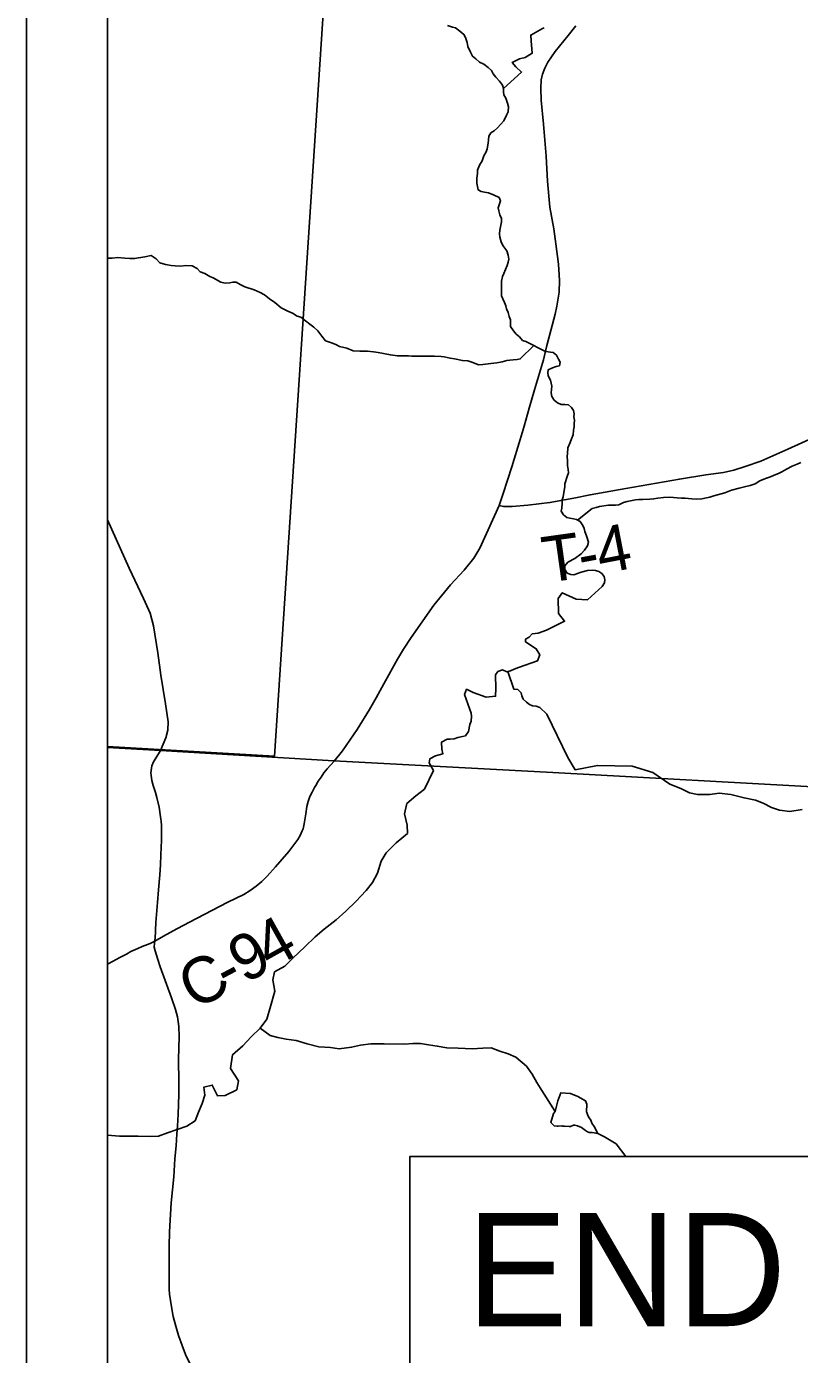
# Model space of a CAD drawing. Extents: x 0 to 34, y 0 to 22.
# Drawn here: x 23.917 to 24.872, y 17.319 to 18.961 of the extents above; entities that cross this region are included whole.
import ezdxf

# ---------------------------------------------------------------- set-up
doc = ezdxf.new("R2010")
doc.units = 0
for name, color, linetype in [('GM_X_Adjacent_County', 7, 'Continuous'), ('GM_X_County', 7, 'Continuous'), ('GM_X_County_Road', 7, 'Continuous'), ('GM_X_County_Road_Text', 7, 'Continuous'), ('GM_X_Minor_Lake', 7, 'Continuous'), ('GM_X_Minor_River', 7, 'Continuous'), ('GM_X_Section', 7, 'Continuous'), ('GM_X_Township', 7, 'Continuous'), ('GM_X_Township_Road', 7, 'Continuous'), ('GM_X_Township_Road_Text', 7, 'Continuous'), ('SH_Data', 7, 'Continuous'), ('SH_Text', 7, 'Continuous')]:
    doc.layers.add(name, color=color, linetype=linetype)

msp = doc.modelspace()

# ---------------------------------------------------------------- linework, layer by layer
at = {"layer": 'GM_X_Adjacent_County'}
for points in [[(30.8167, 17.8174), (30.8167, 20.9), (24.0167, 20.9), (24.0167, 18.0693)], [(24.0167, 18.0693), (24.0167, 14.1), (30.8167, 14.1), (30.8167, 17.8174)], [(25.5999, 17.9814), (24.5675, 18.0386), (24.2964, 18.0528), (24.0824, 18.0658), (24.0167, 18.0693)], [(24.0167, 18.0693), (24.0824, 18.0658), (24.2964, 18.0528), (24.5675, 18.0386), (25.5999, 17.9814)]]:
    msp.add_lwpolyline(points, dxfattribs=at)
at = {"layer": 'GM_X_County'}
for points in [[(30.8167, 17.8174), (30.8167, 20.9), (24.0167, 20.9), (24.0167, 18.0693)], [(24.0167, 18.0693), (24.0824, 18.0658), (24.2964, 18.0528), (24.5675, 18.0386), (25.5999, 17.9814)], [(24.0167, 18.0693), (24.0167, 14.1), (30.8167, 14.1), (30.8167, 17.8174)], [(25.5999, 17.9814), (24.5675, 18.0386), (24.2964, 18.0528), (24.0824, 18.0658), (24.0167, 18.0693)]]:
    msp.add_lwpolyline(points, dxfattribs=at)
at = {"layer": 'GM_X_County_Road'}
for points in [[(24.5957, 18.962), (24.5865, 18.9501), (24.5704, 18.9303), (24.561, 18.9168), (24.5573, 18.9095), (24.5544, 18.9023), (24.553, 18.8952), (24.5525, 18.8844), (24.553, 18.87), (24.556, 18.8404), (24.559, 18.8009), (24.5608, 18.7697), (24.5635, 18.7377), (24.5686, 18.7109), (24.5711, 18.6923), (24.5743, 18.6673), (24.5757, 18.6471), (24.5753, 18.6326), (24.5725, 18.6152), (24.5704, 18.6055), (24.5649, 18.5851), (24.5599, 18.5667), (24.5557, 18.549), (24.5447, 18.5119), (24.5383, 18.4891), (24.5319, 18.4669), (24.5268, 18.4503), (24.5166, 18.4166), (24.5058, 18.3837), (24.501, 18.3689), (24.4876, 18.3387), (24.4772, 18.3159), (24.4698, 18.3036), (24.4576, 18.2889), (24.441, 18.2704), (24.4203, 18.2453), (24.3924, 18.2054), (24.3827, 18.1911), (24.3753, 18.1787), (24.3583, 18.1481), (24.349, 18.1307), (24.3405, 18.1162), (24.3255, 18.0918), (24.3072, 18.0654), (24.2971, 18.0525)], [(24.0754, 17.8299), (24.0859, 17.836), (24.1023, 17.8451), (24.1269, 17.858), (24.1656, 17.8781), (24.1851, 17.8878), (24.1931, 17.8925), (24.2007, 17.8978), (24.2077, 17.9038), (24.2143, 17.9103), (24.2246, 17.9219), (24.2408, 17.9408), (24.2485, 17.9505), (24.2521, 17.9555), (24.2551, 17.9607), (24.2575, 17.9662), (24.2585, 17.969), (24.2599, 17.975), (24.2618, 17.9873), (24.2634, 17.9965), (24.2649, 18.0026), (24.2669, 18.0086), (24.2696, 18.0143), (24.2727, 18.0198), (24.2743, 18.0224), (24.2774, 18.0277), (24.2808, 18.0328), (24.2844, 18.0379), (24.2863, 18.0404), (24.2883, 18.0429), (24.2971, 18.0525)], [(24.1184, 17.3077), (24.1131, 17.3188), (24.1089, 17.3299), (24.1045, 17.3422), (24.1013, 17.3538), (24.098, 17.3655), (24.0957, 17.3778), (24.0935, 17.3932), (24.0931, 17.3995), (24.0928, 17.4277), (24.0929, 17.4525), (24.0936, 17.4705), (24.0953, 17.5061), (24.0986, 17.5385), (24.1, 17.5605), (24.1015, 17.5766), (24.1024, 17.5914), (24.1031, 17.6011), (24.104, 17.6161), (24.1044, 17.6278), (24.105, 17.6407), (24.1051, 17.6561), (24.1045, 17.6834), (24.1052, 17.712), (24.1049, 17.7243), (24.1043, 17.7304), (24.1032, 17.7365), (24.1007, 17.7453), (24.0957, 17.76), (24.0818, 17.798), (24.0788, 17.807), (24.0755, 17.8178), (24.0746, 17.8225), (24.0749, 17.8272), (24.0754, 17.8299)]]:
    msp.add_lwpolyline(points, dxfattribs=at)
at = {"layer": 'GM_X_Minor_Lake'}
for points in [[(24.6232, 17.5922), (24.6184, 17.6007), (24.6154, 17.6046), (24.6142, 17.6084), (24.6123, 17.6115), (24.6107, 17.6142), (24.6092, 17.618), (24.6088, 17.6187), (24.6092, 17.6283), (24.6077, 17.6325), (24.5981, 17.6379), (24.5893, 17.6413), (24.5774, 17.6425), (24.5736, 17.6325), (24.5701, 17.6194)], [(24.5701, 17.6194), (24.5682, 17.6168), (24.5647, 17.6057), (24.5689, 17.6015), (24.5728, 17.6011), (24.5739, 17.6011), (24.5785, 17.6015), (24.5797, 17.6011), (24.5819, 17.6011), (24.5877, 17.6007), (24.5892, 17.6007), (24.5931, 17.6022), (24.5946, 17.6022), (24.5977, 17.6015), (24.603, 17.5996), (24.6076, 17.5957), (24.6103, 17.5942), (24.6122, 17.5934), (24.616, 17.5934), (24.6232, 17.5922)]]:
    msp.add_lwpolyline(points, dxfattribs=at)
at = {"layer": 'GM_X_Minor_River'}
for points in [[(24.5582, 18.5591), (24.5341, 18.5716), (24.53, 18.5727), (24.5262, 18.5772), (24.522, 18.5807), (24.5189, 18.5848), (24.5151, 18.5901), (24.5151, 18.5985), (24.5135, 18.6023), (24.512, 18.6076), (24.5101, 18.6118), (24.5093, 18.6156), (24.5074, 18.6197), (24.5055, 18.6243), (24.504, 18.6281), (24.5039, 18.6463), (24.5051, 18.652), (24.5069, 18.6558), (24.5107, 18.6657), (24.5122, 18.6695), (24.513, 18.6733), (24.5122, 18.6782), (24.5103, 18.6835), (24.5057, 18.6903), (24.5034, 18.6949), (24.5019, 18.7006), (24.5015, 18.7047), (24.5019, 18.7093), (24.503, 18.7154), (24.5037, 18.7195), (24.5037, 18.7237), (24.5018, 18.7283), (24.5007, 18.7332), (24.4999, 18.737), (24.5014, 18.7416), (24.5025, 18.7453), (24.501, 18.7495), (24.4949, 18.7525), (24.4877, 18.7552), (24.4827, 18.7563), (24.4789, 18.7571), (24.4751, 18.759), (24.4732, 18.7673), (24.4736, 18.7734), (24.4743, 18.7795), (24.4743, 18.7836), (24.4766, 18.7897), (24.48, 18.795), (24.4819, 18.8011), (24.4849, 18.806), (24.486, 18.8098), (24.4875, 18.8167), (24.4879, 18.8209), (24.4883, 18.8254), (24.4909, 18.8296), (24.4947, 18.8319), (24.4989, 18.8357), (24.5027, 18.8399), (24.5068, 18.8444), (24.5102, 18.8516), (24.5121, 18.8554), (24.5125, 18.8619), (24.5113, 18.8664), (24.5094, 18.8725), (24.5067, 18.8767), (24.5063, 18.8805), (24.5063, 18.8846), (24.5052, 18.8884), (24.5014, 18.8937), (24.4968, 18.8983), (24.4934, 18.9025), (24.4915, 18.9066), (24.4876, 18.9104), (24.4819, 18.9146), (24.4766, 18.9169), (24.472, 18.921), (24.4682, 18.9244), (24.4656, 18.9294), (24.4621, 18.9362), (24.4613, 18.9415), (24.4594, 18.9476), (24.4575, 18.9514), (24.4522, 18.9555), (24.4472, 18.9593), (24.4434, 18.9604), (24.4373, 18.9623)], [(24.5063, 18.8846), (24.5287, 18.9048), (24.5215, 18.9112), (24.5169, 18.9165), (24.526, 18.9211), (24.5332, 18.9226), (24.5419, 18.928), (24.5404, 18.9435), (24.54, 18.9504), (24.5544, 18.9587), (24.5565, 18.9594)], [(24.5439, 18.5665), (24.527, 18.5499), (24.5232, 18.5492), (24.5183, 18.5488), (24.5141, 18.5484), (24.5103, 18.548), (24.5046, 18.5465), (24.4981, 18.5453), (24.4905, 18.5442), (24.481, 18.543), (24.4753, 18.5426), (24.4685, 18.5456), (24.4624, 18.5475), (24.4556, 18.5479), (24.4457, 18.5502), (24.4404, 18.5509), (24.4331, 18.5524), (24.4293, 18.5528), (24.421, 18.5535), (24.3932, 18.5535), (24.3887, 18.5539), (24.3754, 18.5538), (24.3666, 18.555), (24.3514, 18.558), (24.3457, 18.5587), (24.3381, 18.5595), (24.3286, 18.5595), (24.3206, 18.5598), (24.3127, 18.5632), (24.3035, 18.5655), (24.299, 18.5678), (24.2936, 18.5697), (24.2864, 18.5723), (24.2818, 18.578), (24.2769, 18.5848), (24.2719, 18.5894), (24.267, 18.5931), (24.2617, 18.5969), (24.2556, 18.6015), (24.2514, 18.603), (24.2453, 18.6064), (24.2396, 18.609), (24.2316, 18.6132), (24.2236, 18.6196), (24.2171, 18.6242), (24.2107, 18.6291), (24.2057, 18.6321), (24.1981, 18.6355), (24.1867, 18.6393), (24.1806, 18.642), (24.1757, 18.645), (24.1719, 18.645), (24.1681, 18.6442), (24.1624, 18.6438), (24.157, 18.645), (24.1475, 18.6503), (24.1433, 18.6518), (24.1369, 18.6556), (24.1315, 18.6578), (24.1274, 18.662), (24.1216, 18.665), (24.1137, 18.6654), (24.1076, 18.6646), (24.1004, 18.665), (24.0954, 18.6657), (24.0886, 18.6669), (24.0814, 18.6688), (24.0768, 18.6737), (24.0707, 18.6778), (24.0627, 18.6763), (24.0502, 18.674), (24.0445, 18.674), (24.038, 18.6748), (24.0297, 18.6755), (24.0225, 18.6747), (24.0167, 18.6747)], [(24.5596, 18.2144), (24.5818, 18.2256), (24.5742, 18.235), (24.5738, 18.2536), (24.579, 18.2608), (24.5961, 18.2529), (24.6101, 18.2522), (24.6283, 18.2685), (24.6313, 18.2731), (24.6317, 18.2769), (24.6309, 18.2807), (24.6279, 18.2845), (24.6241, 18.2871), (24.6203, 18.2882), (24.6161, 18.2886), (24.6104, 18.2882), (24.6025, 18.2863), (24.5934, 18.2829), (24.5896, 18.2833), (24.585, 18.2851), (24.582, 18.2897), (24.582, 18.2942), (24.5861, 18.2988), (24.5945, 18.303), (24.6024, 18.3091), (24.6065, 18.3133), (24.6103, 18.319), (24.6114, 18.3235), (24.6091, 18.3311), (24.6069, 18.3364), (24.6061, 18.3402), (24.6046, 18.344), (24.6011, 18.3489), (24.5966, 18.3512), (24.5928, 18.3523), (24.5882, 18.3531), (24.5845, 18.3538), (24.5807, 18.3572), (24.5776, 18.3618), (24.5784, 18.3656), (24.5787, 18.3716), (24.5791, 18.3758), (24.5802, 18.3796), (24.5809, 18.3849), (24.5821, 18.3917), (24.5824, 18.3955), (24.5851, 18.4047), (24.5866, 18.4092), (24.5862, 18.4134), (24.5854, 18.4183), (24.5854, 18.424), (24.585, 18.4293), (24.5854, 18.4331), (24.5861, 18.4399), (24.5887, 18.4468), (24.5906, 18.4513), (24.5925, 18.4563), (24.5928, 18.462), (24.5936, 18.4661), (24.5936, 18.4699), (24.5943, 18.4741), (24.5932, 18.4783), (24.5939, 18.4821), (24.5928, 18.4862), (24.5905, 18.49), (24.5867, 18.4934), (24.5821, 18.4938), (24.5776, 18.4938), (24.573, 18.4957), (24.5692, 18.4991), (24.5662, 18.5036), (24.5654, 18.5082), (24.5658, 18.512), (24.5662, 18.5162), (24.5654, 18.52), (24.5646, 18.5237), (24.5616, 18.5291), (24.5612, 18.5328), (24.5616, 18.5366), (24.5669, 18.5389), (24.5714, 18.5405), (24.5756, 18.5416), (24.5763, 18.5458), (24.5744, 18.5496), (24.5721, 18.5545), (24.5679, 18.5579), (24.5582, 18.5591)], [(24.5979, 18.3505), (24.6159, 18.3649), (24.6208, 18.3664), (24.625, 18.3676), (24.6363, 18.3691), (24.645, 18.3691), (24.6488, 18.3695), (24.6549, 18.3725), (24.6594, 18.3737), (24.6696, 18.3756), (24.6738, 18.376), (24.6787, 18.376), (24.6871, 18.3764), (24.692, 18.3768), (24.6973, 18.3779), (24.7041, 18.3787), (24.7113, 18.3791), (24.7166, 18.3787), (24.7212, 18.378), (24.7265, 18.3776), (24.731, 18.3776), (24.7394, 18.3769), (24.7447, 18.3765), (24.7515, 18.3769), (24.7572, 18.3781), (24.7613, 18.3792), (24.7663, 18.3807), (24.7799, 18.3842), (24.7882, 18.3876), (24.7977, 18.3903), (24.806, 18.3922), (24.8113, 18.3934), (24.8174, 18.3956), (24.8234, 18.3991), (24.8302, 18.4021), (24.8367, 18.404), (24.8412, 18.4063), (24.8465, 18.4082), (24.8507, 18.4105), (24.8563, 18.4136), (24.8632, 18.4174), (24.8696, 18.42), (24.8741, 18.4219)], [(24.5596, 18.2144), (24.5492, 18.211), (24.5419, 18.2098), (24.5382, 18.206), (24.5336, 18.2034), (24.5336, 18.1999), (24.5469, 18.1916), (24.5511, 18.184), (24.5485, 18.1764), (24.525, 18.1684), (24.5196, 18.1661), (24.5151, 18.1642), (24.5105, 18.1631), (24.5052, 18.1654), (24.4995, 18.1635), (24.4965, 18.1593), (24.4969, 18.1422), (24.4965, 18.1327), (24.4848, 18.1315), (24.4688, 18.1376), (24.4608, 18.1414), (24.4582, 18.1349), (24.4662, 18.1118), (24.467, 18.108), (24.4662, 18.1019), (24.4647, 18.0977), (24.4632, 18.089), (24.4594, 18.084), (24.4556, 18.0829), (24.4499, 18.0818), (24.4454, 18.0802), (24.4405, 18.0798), (24.4367, 18.0798), (24.4298, 18.076), (24.4302, 18.0673), (24.4314, 18.0616), (24.4223, 18.0589), (24.4154, 18.0555), (24.4143, 18.0506), (24.4198, 18.0411)], [(24.5119, 18.1634), (24.5193, 18.1415), (24.5239, 18.1411), (24.5281, 18.1369), (24.5292, 18.1331), (24.5308, 18.1293), (24.5346, 18.1255), (24.5384, 18.1225), (24.5422, 18.121), (24.5467, 18.1206), (24.5513, 18.1187), (24.56, 18.1108)], [(24.56, 18.1108), (24.5861, 18.0571), (24.5948, 18.0419), (24.6225, 18.0473), (24.6653, 18.0463), (24.6911, 18.0383), (24.7121, 18.0239)], [(24.3877, 17.9632), (24.3873, 17.9734), (24.3838, 17.9875), (24.3868, 18), (24.3981, 18.0095), (24.4087, 18.0179), (24.4198, 18.0411)], [(24.7121, 18.0239), (24.7255, 18.0186), (24.7365, 18.0133), (24.7463, 18.0114), (24.7614, 18.0111), (24.7732, 18.013), (24.7876, 18.0112), (24.8039, 18.0071), (24.8179, 18.0041), (24.8274, 18.0007), (24.8376, 17.995), (24.8478, 17.992), (24.8603, 17.9902), (24.8755, 17.9929)], [(24.0167, 17.59), (24.0216, 17.5895), (24.0315, 17.5888), (24.0447, 17.5888), (24.0546, 17.5889), (24.0702, 17.5882), (24.08, 17.5886), (24.091, 17.5928), (24.1149, 17.6009), (24.1251, 17.6077), (24.1292, 17.6184), (24.1337, 17.629), (24.1371, 17.6393), (24.1359, 17.6495), (24.1462, 17.6518), (24.1527, 17.6386), (24.1622, 17.639), (24.1765, 17.6462), (24.1788, 17.6573), (24.1689, 17.6724), (24.1714, 17.6895), (24.1839, 17.7005), (24.1945, 17.7116), (24.2054, 17.7223), (24.2137, 17.7333), (24.2182, 17.7489), (24.2235, 17.7679), (24.2211, 17.7819), (24.2234, 17.7918), (24.2362, 17.799), (24.2457, 17.8089), (24.2608, 17.8227), (24.2733, 17.8352), (24.2846, 17.8448), (24.2994, 17.8562), (24.3115, 17.8669), (24.3239, 17.8791), (24.3364, 17.8924), (24.3443, 17.9023), (24.3504, 17.9141), (24.3552, 17.9289), (24.3612, 17.9392), (24.3737, 17.9517), (24.3877, 17.9632)], [(24.2054, 17.7223), (24.218, 17.7132), (24.2275, 17.7106), (24.2378, 17.7087), (24.2499, 17.7072), (24.2636, 17.7031), (24.278, 17.6993), (24.2924, 17.6982), (24.3031, 17.6968), (24.3186, 17.6987), (24.3296, 17.7014), (24.3425, 17.703), (24.3588, 17.703), (24.3839, 17.7023), (24.3941, 17.7035), (24.4036, 17.7032), (24.4135, 17.7017), (24.4245, 17.7002), (24.4362, 17.698), (24.4503, 17.6976), (24.4677, 17.6966), (24.481, 17.6974), (24.4913, 17.6978), (24.5019, 17.694), (24.5122, 17.6906), (24.5217, 17.6865), (24.5346, 17.6751), (24.5419, 17.6653), (24.5476, 17.6551), (24.5537, 17.6452)], [(24.5537, 17.6452), (24.5701, 17.6194)], [(24.6232, 17.5922), (24.6312, 17.5877), (24.6456, 17.5794), (24.6577, 17.5637)]]:
    msp.add_lwpolyline(points, dxfattribs=at)
at = {"layer": 'GM_X_Section'}
msp.add_line((24.0167, 19.0779), (24.0167, 18.0707), dxfattribs=at)
msp.add_lwpolyline([(24.0167, 18.0707), (24.2233, 18.0587), (24.2888, 19.0593), (24.0167, 19.0779)], dxfattribs=at)
at = {"layer": 'GM_X_Township'}
for points in [[(26.3564, 20.9), (24.0167, 20.9), (24.0167, 18.0693)], [(24.0167, 18.0693), (24.0824, 18.0658), (24.2964, 18.0528), (24.5675, 18.0386), (25.5999, 17.9814)], [(25.5999, 17.9814), (24.5675, 18.0386), (24.2964, 18.0528), (24.0824, 18.0658), (24.0167, 18.0693)], [(24.0167, 18.0693), (24.0167, 14.1), (26.1244, 14.1)]]:
    msp.add_lwpolyline(points, dxfattribs=at)
at = {"layer": 'GM_X_Township_Road'}
for points in [[(24.501, 18.3689), (24.5063, 18.3675), (24.5171, 18.3673), (24.5366, 18.3691), (24.5637, 18.3724), (24.5934, 18.3779), (24.6135, 18.382), (24.6577, 18.3899), (24.7239, 18.4014), (24.7566, 18.4065), (24.7783, 18.4097), (24.7912, 18.4125), (24.8053, 18.4171), (24.8247, 18.4235), (24.8579, 18.4385), (24.9316, 18.4717)], [(24.0824, 18.0658), (24.0889, 18.0812), (24.0914, 18.0907), (24.0918, 18.1011), (24.0886, 18.1234), (24.0825, 18.159), (24.0791, 18.1863), (24.0736, 18.2198), (24.0694, 18.2354), (24.0614, 18.2535), (24.0435, 18.2914), (24.0167, 18.3509)], [(24.0754, 17.8299), (24.0761, 17.8406), (24.0762, 17.8436), (24.0767, 17.8529), (24.0786, 17.8777), (24.0799, 17.8933), (24.0813, 17.9119), (24.0821, 17.9242), (24.0827, 17.9365), (24.0834, 17.9548), (24.0836, 17.964), (24.0835, 17.97), (24.0834, 17.973), (24.083, 17.9781), (24.0827, 17.9808), (24.082, 17.9866), (24.0811, 17.9926), (24.0805, 17.9956), (24.0777, 18.0077), (24.0759, 18.0136), (24.0732, 18.0226), (24.0716, 18.0287), (24.0707, 18.0349), (24.0705, 18.038), (24.0706, 18.041), (24.071, 18.0439), (24.0717, 18.0466), (24.0738, 18.0516), (24.0764, 18.0563), (24.0824, 18.0658)], [(24.0167, 17.8013), (24.0184, 17.8023), (24.0321, 17.8096), (24.0402, 17.814), (24.0457, 17.8169), (24.0541, 17.8208), (24.0597, 17.8231), (24.0693, 17.827), (24.0754, 17.8299)]]:
    msp.add_lwpolyline(points, dxfattribs=at)
at = {"layer": 'SH_Data'}
for points in [[(23.9167, 21), (30.9167, 21), (30.9167, 14), (23.9167, 14)], [(24.0167, 20.9), (30.8167, 20.9), (30.8167, 14.1), (24.0167, 14.1)]]:
    msp.add_lwpolyline(points, close=True, dxfattribs=at)
at = {"layer": 'SH_Text'}
msp.add_lwpolyline([(24.3906, 17.0737), (25.8632, 17.0737), (25.8632, 17.5637), (24.3906, 17.5637)], close=True, dxfattribs=at)

# ---------------------------------------------------------------- texts
at = {"layer": 'GM_X_County_Road_Text'}
for s, rotation, p in [('4', 29.1871, (24.2182, 17.7939)), ('9', 28.0653, (24.1862, 17.7768)), ('C', 27.7887, (24.1241, 17.744)), ('-', 27.8495, (24.1654, 17.7658))]:
    msp.add_text(s, height=0.0568, rotation=rotation, dxfattribs=at).set_placement(p)
at = {"layer": 'GM_X_Township_Road_Text'}
for s, rotation, p in [('4', 10.9492, (24.6266, 18.2836)), ('T', 7.9756, (24.5584, 18.2729)), ('-', 10.5235, (24.6032, 18.2792))]:
    msp.add_text(s, height=0.0568, rotation=rotation, dxfattribs=at).set_placement(p)
at = {"layer": 'SH_Text'}
msp.add_text('END PROJECT', height=0.14, dxfattribs=at).set_placement((24.4606, 17.3537))

doc.saveas('drawing.dxf')
